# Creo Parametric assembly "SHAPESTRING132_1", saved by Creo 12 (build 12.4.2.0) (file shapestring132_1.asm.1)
Units: Custom; MM, KILOGRAM, SECS

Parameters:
  PTC_WM_ITERATION = "0"
  PTC_WM_VERSION = "-.0"
  PTC_WM_LIFECYCLE_STATE = "In Work"
  PTC_WM_LIFECYCLE = "MO_CADDocument"
  PTC_WM_CREATED_BY = "Maximilian Roepper (Z0017RMS: MO)"
  PTC_WM_CREATED_ON = "18-Sep-26 11:36:42 AM"
  PTC_WM_MODIFIED_BY = "Maximilian Roepper (Z0017RMS: MO)"
  PTC_WM_MODIFIED_ON = "18-Sep-26 11:36:46 AM"
  PDMLINKNUMBER = "PDM000071455341"
  PTC_WM_NUMBER = "PDM000071455341"

Other parameters: WEIGHT, WEIGHT_FACTOR, WEIGHT_ADD, MC_ERRORS, SUPPLIER

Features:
  1. coordinate system
  2. imported feature
  3. component "SHAPESTRING073_1"
  4. component "SHAPESTRING128_1"
  5. component "SHAPESTRING129_1"
  6. component "SHAPESTRING130_1"
  7. component "SHAPESTRING131_1"

Other named items: DRW_VIEW_ORG, ROUGH-GROB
